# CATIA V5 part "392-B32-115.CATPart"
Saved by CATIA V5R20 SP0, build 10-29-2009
Part number: 392-B32-115
Definition: NONE
Nomenclature: 392-B32-115
Source: Unknown
Description: 392-B32-115
Bounding box of the stored display mesh (mm): x 0 to 115, y -15.621 to 15.621, z -15.5 to 15.5
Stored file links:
  C:\Users\Utente\Desktop\IO LAVORO\3D X SITO CF\X SITO\3D files 392B\392-B32-115.CATPart
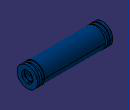
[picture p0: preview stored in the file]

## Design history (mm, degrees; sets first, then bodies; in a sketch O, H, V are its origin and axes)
Body1 "392-B32-115" (main body)
  Solid1: solid without history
